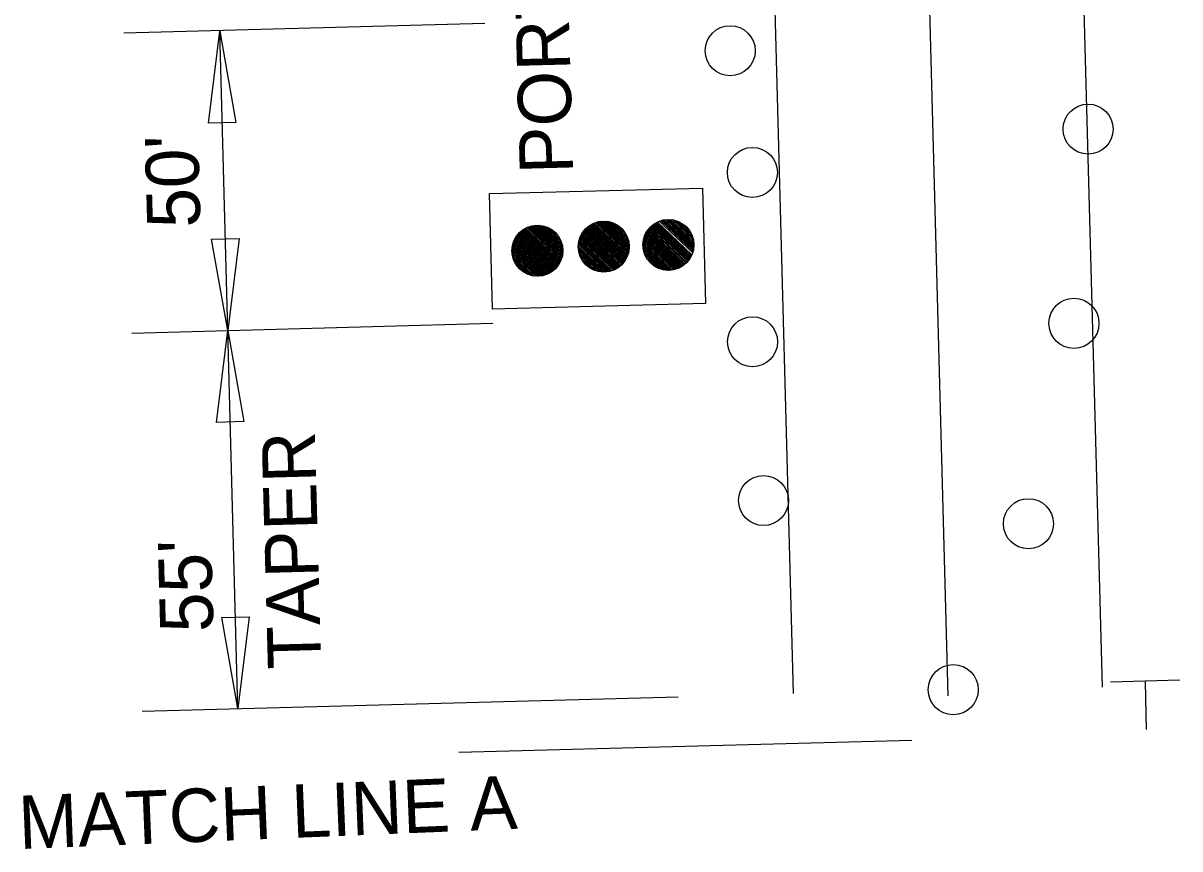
# Model space of a CAD drawing. Extents: x 1926836 to 1933254, y 596317 to 604524.
# Drawn here: x 1931166.2 to 1931299.4, y 598536.9 to 598632 of the extents above; entities that cross this region are included whole.
import ezdxf

# ---------------------------------------------------------------- set-up
doc = ezdxf.new("R2010")
doc.units = 0
doc.layers.add('Default', color=7, linetype='Continuous')

msp = doc.modelspace()

# ---------------------------------------------------------------- linework, layer by layer
at = {"layer": 'Default'}
for p, q in [((1931290.49, 598555.52), (1931286.36, 598709.57)), ((1931272.72, 598554.54), (1931268.69, 598704.83)), ((1931254.92, 598554.79), (1931250.95, 598702.88)), ((1931177.8, 598630.87), (1931219.37, 598631.98)), ((1931187.54, 598620.47), (1931188.84, 598631.05)), ((1931189.76, 598596.61), (1931188.84, 598631.05)), ((1931188.84, 598631.05), (1931190.7, 598620.56)), ((1931190.7, 598620.56), (1931187.54, 598620.47)), ((1931228.05, 598604.45), (1931223.95, 598608.33)), ((1931228.1, 598604.57), (1931224.07, 598608.39)), ((1931228.16, 598604.69), (1931224.19, 598608.45)), ((1931228.21, 598604.82), (1931224.32, 598608.51)), ((1931228.25, 598604.96), (1931224.45, 598608.56)), ((1931228.29, 598605.1), (1931224.59, 598608.61)), ((1931228.32, 598605.25), (1931224.73, 598608.64)), ((1931228.34, 598605.4), (1931224.89, 598608.68)), ((1931228.36, 598605.56), (1931225.04, 598608.7)), ((1931228.37, 598605.73), (1931225.21, 598608.72)), ((1931228.36, 598605.91), (1931225.39, 598608.73)), ((1931228.35, 598606.1), (1931225.58, 598608.72)), ((1931228.32, 598606.3), (1931225.79, 598608.7)), ((1931228.27, 598606.52), (1931226.01, 598608.67)), ((1931228.2, 598606.77), (1931226.26, 598608.61)), ((1931228.07, 598607.06), (1931226.56, 598608.5)), ((1931235.25, 598604.28), (1931230.98, 598608.33)), ((1931235.34, 598604.38), (1931231.08, 598608.42)), ((1931235.42, 598604.48), (1931231.17, 598608.5)), ((1931235.49, 598604.59), (1931231.27, 598608.59)), ((1931235.56, 598604.69), (1931231.38, 598608.66)), ((1931235.63, 598604.81), (1931231.49, 598608.74)), ((1931235.69, 598604.92), (1931231.6, 598608.8)), ((1931235.75, 598605.04), (1931231.72, 598608.87)), ((1931235.81, 598605.17), (1931231.84, 598608.93)), ((1931235.85, 598605.3), (1931231.97, 598608.98)), ((1931235.9, 598605.43), (1931232.1, 598609.04)), ((1931235.94, 598605.58), (1931232.24, 598609.08)), ((1931235.97, 598605.72), (1931232.38, 598609.12)), ((1931235.99, 598605.88), (1931232.53, 598609.15)), ((1931236.01, 598606.04), (1931232.69, 598609.18)), ((1931236.02, 598606.2), (1931232.86, 598609.19)), ((1931236.01, 598606.38), (1931233.04, 598609.2)), ((1931236, 598606.57), (1931233.23, 598609.2)), ((1931235.97, 598606.78), (1931233.43, 598609.18)), ((1931235.92, 598607), (1931233.66, 598609.14)), ((1931235.85, 598607.25), (1931233.91, 598609.08)), ((1931235.72, 598607.54), (1931234.21, 598608.97)), ((1931235.49, 598607.93), (1931234.61, 598608.77)), ((1931242.55, 598604.34), (1931238.29, 598608.38)), ((1931242.64, 598604.43), (1931238.37, 598608.48)), ((1931242.73, 598604.53), (1931238.46, 598608.57)), ((1931242.81, 598604.62), (1931238.55, 598608.66)), ((1931242.89, 598604.73), (1931238.65, 598608.74)), ((1931242.96, 598604.83), (1931238.75, 598608.82)), ((1931243.03, 598604.94), (1931238.86, 598608.89)), ((1931243.1, 598605.06), (1931238.97, 598608.97)), ((1931243.16, 598605.18), (1931239.09, 598609.03)), ((1931243.21, 598605.3), (1931239.21, 598609.1)), ((1931243.31, 598605.56), (1931239.46, 598609.21)), ((1931243.35, 598605.7), (1931239.6, 598609.26)), ((1931243.39, 598605.84), (1931239.74, 598609.3)), ((1931243.41, 598605.99), (1931239.89, 598609.33)), ((1931243.44, 598606.15), (1931240.04, 598609.36)), ((1931243.45, 598606.31), (1931240.2, 598609.39)), ((1931243.45, 598606.48), (1931240.38, 598609.4)), ((1931243.45, 598606.66), (1931240.56, 598609.4)), ((1931243.43, 598606.86), (1931240.75, 598609.39)), ((1931243.39, 598607.07), (1931240.97, 598609.37)), ((1931243.33, 598607.3), (1931241.2, 598609.32)), ((1931243.24, 598607.57), (1931241.47, 598609.24)), ((1931243.08, 598607.89), (1931241.8, 598609.1)), ((1931242.67, 598608.45), (1931242.39, 598608.73)), ((1931187.9, 598607.11), (1931191.06, 598607.19)), ((1931189.76, 598596.61), (1931187.9, 598607.11)), ((1931191.06, 598607.19), (1931189.76, 598596.61)), ((1931226.78, 598603.18), (1931222.75, 598607)), ((1931226.9, 598603.24), (1931222.81, 598607.12)), ((1931227.01, 598603.31), (1931222.87, 598607.24)), ((1931227.12, 598603.38), (1931222.94, 598607.35)), ((1931227.23, 598603.46), (1931223.01, 598607.46)), ((1931227.33, 598603.54), (1931223.08, 598607.56)), ((1931227.42, 598603.63), (1931223.16, 598607.67)), ((1931227.52, 598603.72), (1931223.25, 598607.76)), ((1931227.6, 598603.81), (1931223.33, 598607.85)), ((1931227.69, 598603.91), (1931223.43, 598607.94)), ((1931227.77, 598604.01), (1931223.52, 598608.03)), ((1931227.84, 598604.11), (1931223.62, 598608.11)), ((1931227.92, 598604.22), (1931223.73, 598608.19)), ((1931227.98, 598604.33), (1931223.84, 598608.26)), ((1931227.85, 598607.46), (1931226.96, 598608.29)), ((1931234.05, 598603.48), (1931230.25, 598607.09)), ((1931234.18, 598603.54), (1931230.29, 598607.22)), ((1931234.31, 598603.59), (1931230.34, 598607.35)), ((1931234.43, 598603.65), (1931230.4, 598607.48)), ((1931234.55, 598603.72), (1931230.45, 598607.6)), ((1931234.66, 598603.78), (1931230.52, 598607.71)), ((1931234.77, 598603.86), (1931230.58, 598607.83)), ((1931234.88, 598603.94), (1931230.66, 598607.94)), ((1931234.98, 598604.02), (1931230.73, 598608.04)), ((1931235.07, 598604.1), (1931230.81, 598608.14)), ((1931235.17, 598604.19), (1931230.9, 598608.24)), ((1931241.27, 598603.62), (1931237.63, 598607.06)), ((1931241.41, 598603.66), (1931237.67, 598607.21)), ((1931241.55, 598603.71), (1931237.71, 598607.35)), ((1931241.68, 598603.76), (1931237.75, 598607.48)), ((1931241.8, 598603.82), (1931237.8, 598607.61)), ((1931241.92, 598603.88), (1931237.86, 598607.73)), ((1931242.04, 598603.95), (1931237.92, 598607.85)), ((1931242.15, 598604.02), (1931237.98, 598607.96)), ((1931242.26, 598604.09), (1931238.05, 598608.08)), ((1931242.36, 598604.17), (1931238.13, 598608.18)), ((1931242.46, 598604.25), (1931238.2, 598608.28)), ((1931225.64, 598602.85), (1931222.48, 598605.84)), ((1931225.81, 598602.87), (1931222.49, 598606.01)), ((1931225.46, 598602.84), (1931222.49, 598605.66)), ((1931225.97, 598602.89), (1931222.51, 598606.17)), ((1931226.12, 598602.93), (1931222.53, 598606.32)), ((1931226.26, 598602.97), (1931222.56, 598606.47)), ((1931226.4, 598603.01), (1931222.6, 598606.61)), ((1931226.53, 598603.06), (1931222.65, 598606.75)), ((1931226.66, 598603.12), (1931222.69, 598606.88)), ((1931233.29, 598603.33), (1931230.13, 598606.32)), ((1931233.46, 598603.34), (1931230.14, 598606.49)), ((1931233.11, 598603.32), (1931230.14, 598606.14)), ((1931232.92, 598603.32), (1931230.15, 598605.95)), ((1931233.62, 598603.37), (1931230.16, 598606.65)), ((1931233.77, 598603.4), (1931230.18, 598606.8)), ((1931232.72, 598603.34), (1931230.18, 598605.75)), ((1931233.91, 598603.44), (1931230.21, 598606.95)), ((1931240.8, 598603.53), (1931237.57, 598606.59)), ((1931240.63, 598603.52), (1931237.57, 598606.42)), ((1931240.96, 598603.55), (1931237.58, 598606.76)), ((1931240.44, 598603.52), (1931237.58, 598606.23)), ((1931241.12, 598603.58), (1931237.6, 598606.91)), ((1931240.25, 598603.53), (1931237.6, 598606.04)), ((1931240.03, 598603.56), (1931237.64, 598605.82)), ((1931225.27, 598602.85), (1931222.5, 598605.47)), ((1931225.07, 598602.87), (1931222.53, 598605.27)), ((1931224.84, 598602.9), (1931222.58, 598605.05)), ((1931224.59, 598602.96), (1931222.65, 598604.8)), ((1931224.29, 598603.07), (1931222.77, 598604.51)), ((1931232.49, 598603.38), (1931230.23, 598605.52)), ((1931232.24, 598603.44), (1931230.3, 598605.28)), ((1931231.94, 598603.54), (1931230.42, 598604.98)), ((1931231.54, 598603.75), (1931230.65, 598604.59)), ((1931239.79, 598603.61), (1931237.7, 598605.59)), ((1931239.52, 598603.69), (1931237.8, 598605.32)), ((1931239.18, 598603.84), (1931237.96, 598604.99)), ((1931223.89, 598603.28), (1931223, 598604.12)), ((1931178.73, 598596.31), (1931220.29, 598597.43)), ((1931188.46, 598586.03), (1931189.76, 598596.61)), ((1931190.93, 598553.07), (1931189.76, 598596.61)), ((1931189.76, 598596.61), (1931191.63, 598586.11)), ((1931191.63, 598586.11), (1931188.46, 598586.03)), ((1931189.07, 598563.56), (1931192.23, 598563.65)), ((1931190.93, 598553.07), (1931189.07, 598563.56)), ((1931192.23, 598563.65), (1931190.93, 598553.07)), ((1931291.41, 598556.15), (1931299.41, 598556.37)), ((1931295.4, 598556.14), (1931295.54, 598550.68)), ((1931179.9, 598552.77), (1931241.63, 598554.43)), ((1931216.36, 598548.05), (1931268.56, 598549.45))]:
    msp.add_line(p, q, dxfattribs=at)
msp.add_lwpolyline([(1931220.25, 598599.07), (1931219.89, 598612.36), (1931244.42, 598613.01), (1931244.78, 598599.73)], close=True, dxfattribs=at)
for centre, radius in [((1931247.63, 598628.82), 2.88), ((1931288.84, 598619.79), 2.88), ((1931250.18, 598614.8), 2.88), ((1931225.43, 598605.79), 2.94), ((1931233.07, 598606.26), 2.94), ((1931240.51, 598606.46), 2.94), ((1931287.22, 598597.43), 2.88), ((1931250.2, 598595.31), 2.88), ((1931251.47, 598577.03), 2.88), ((1931281.97, 598574.36), 2.88), ((1931273.32, 598555.25), 2.88)]:
    msp.add_circle(centre, radius, dxfattribs=at)

# ---------------------------------------------------------------- texts
for s, height, rotation, p in [('PORTABLE TRAFFIC SIGNAL SYSTEM', 6.1396, 91.5377, (1931229.54, 598614.71)), ("50'", 6.14, 91.5377, (1931186.63, 598608.5)), ('TAPER', 6.14, 91.5377, (1931200.53, 598557.7)), ("  55' ", 6.14, 91.5377, (1931188.25, 598557.37)), ('MATCH LINE A', 6.1396, 2.3436, (1931165.78, 598536.89))]:
    msp.add_text(s, height=height, rotation=rotation, dxfattribs=at).set_placement(p)

doc.saveas('drawing.dxf')
